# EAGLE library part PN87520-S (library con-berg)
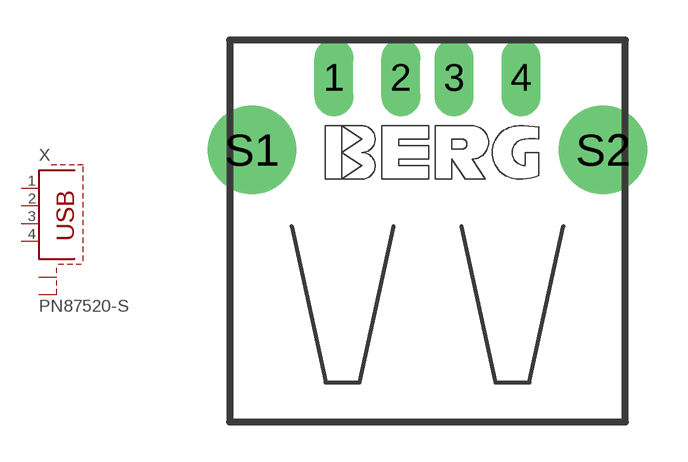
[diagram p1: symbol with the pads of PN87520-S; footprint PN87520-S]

Designator prefix X

## PN87520-S (OC_FARNELL: unknown; OC_NEWARK: unknown)  [PN87520-S]
1  1  pas
2  2  pas
3  3  pas
4  4  pas
S1  S1  pas
S2  S2  pas

## Footprint PN87520-S (pad centres in mm)
USB connector with shield
drill 0.95 long: 1 -3.5,2.71; 2 -1,2.71; 3 1,2.71; 4 3.5,2.71
drill 2.3 pad 2.9 round: S1 -6.57,0; S2 6.57,0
